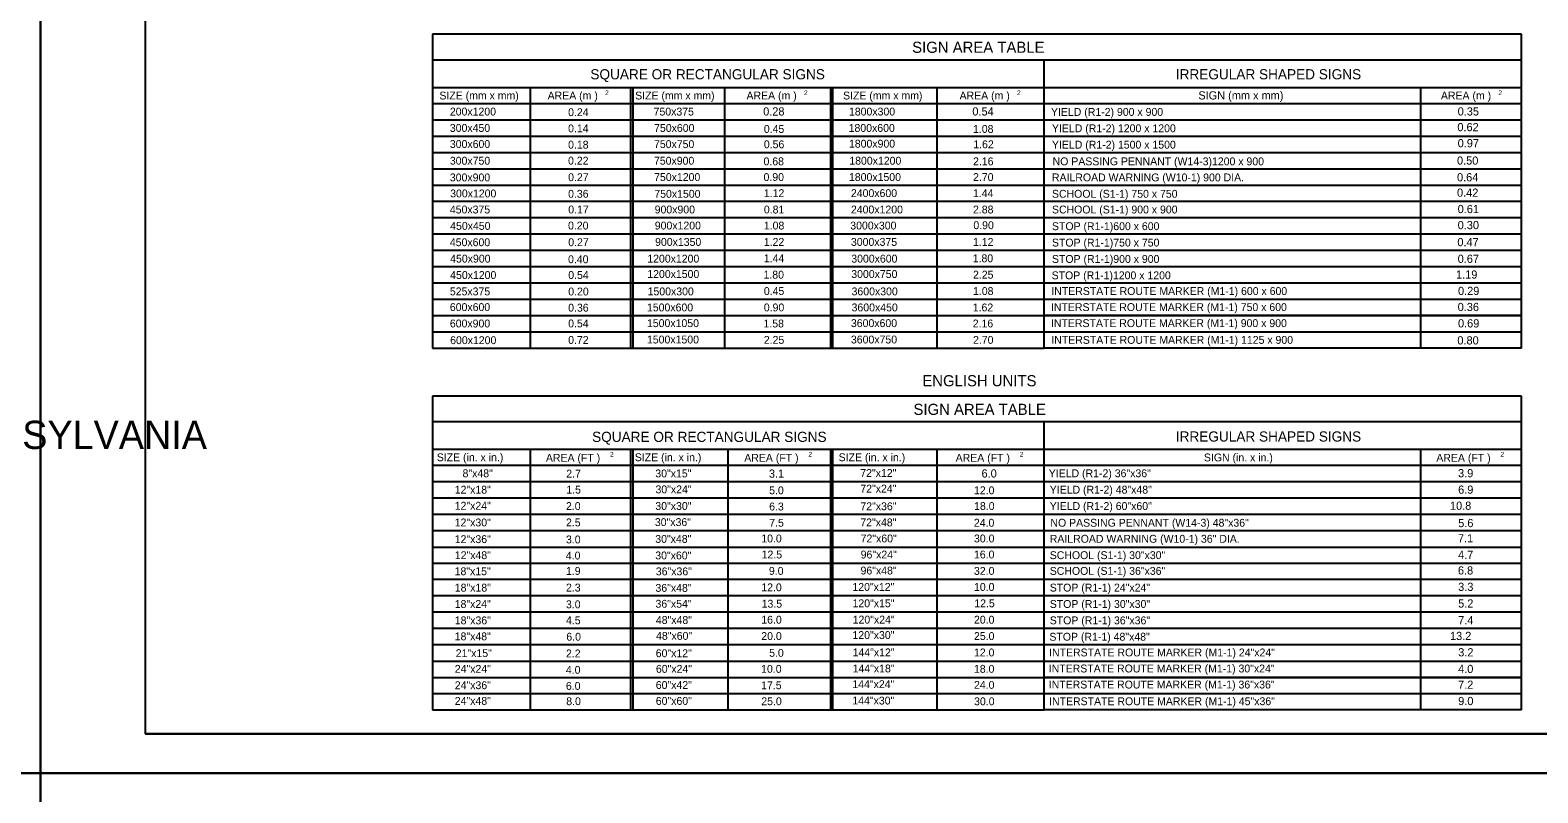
# Model space of a CAD drawing. Extents: x 644358 to 648627, y 294594 to 295782.
# Drawn here: x 646877 to 647453, y 295180 to 295471 of the extents above; entities that cross this region are included whole.
import ezdxf

# ---------------------------------------------------------------- set-up
doc = ezdxf.new("R2010")
doc.units = 0
for name, color, linetype in [('1', 7, 'Continuous'), ('2', 7, 'Continuous'), ('4', 7, 'Continuous'), ('PLT-BNDY', 7, 'Continuous')]:
    doc.layers.add(name, color=color, linetype=linetype)

msp = doc.modelspace()

# ---------------------------------------------------------------- linework, layer by layer
at = {"layer": '1'}
for p, q in [((646921.31, 295766.63), (646921.31, 295202.63)), ((647707.31, 295202.63), (646921.31, 295202.63)), ((646921.31, 295202.63), (647507.31, 295202.63))]:
    msp.add_line(p, q, dxfattribs=at)
at = {"layer": '2'}
for p, q in [((647030.99, 295469.63), (647030.99, 295349.88)), ((647446.74, 295469.63), (647030.99, 295469.63)), ((647446.74, 295349.88), (647446.74, 295469.63)), ((647446.74, 295459.75), (647030.99, 295459.75)), ((647264.37, 295459.75), (647264.37, 295349.88)), ((647030.99, 295449.38), (647446.74, 295449.38)), ((647068.24, 295449.38), (647068.24, 295349.88)), ((647106.62, 295449.38), (647106.62, 295349.88)), ((647107.49, 295449.38), (647107.49, 295349.88)), ((647142.49, 295449.38), (647142.49, 295349.88)), ((647182.99, 295449.38), (647182.99, 295349.88)), ((647183.74, 295449.38), (647183.74, 295349.88)), ((647223.49, 295449.38), (647223.49, 295349.88)), ((647408.37, 295349.88), (647408.37, 295449.38)), ((647030.99, 295443.25), (647446.74, 295443.25)), ((647030.99, 295437), (647446.74, 295437)), ((647030.99, 295430.75), (647446.74, 295430.75)), ((647030.99, 295424.5), (647446.74, 295424.5)), ((647030.99, 295418.25), (647446.74, 295418.25)), ((647030.99, 295412), (647446.74, 295412)), ((647030.99, 295405.88), (647446.74, 295405.88)), ((647030.99, 295399.75), (647446.74, 295399.75)), ((647030.99, 295393.5), (647446.74, 295393.5)), ((647030.99, 295387.25), (647446.74, 295387.25)), ((647030.99, 295381), (647446.74, 295381)), ((647030.99, 295374.75), (647446.74, 295374.75)), ((647030.99, 295368.5), (647446.74, 295368.5)), ((647264.37, 295368.5), (647446.74, 295368.5)), ((647030.99, 295362.25), (647446.74, 295362.25)), ((647446.74, 295362.25), (647264.37, 295362.25)), ((647030.99, 295356.13), (647446.74, 295356.13)), ((647030.99, 295349.88), (647264.37, 295349.88)), ((647446.74, 295349.88), (647264.37, 295349.88)), ((647030.99, 295331.57), (647030.99, 295211.82)), ((647446.74, 295331.57), (647030.99, 295331.57)), ((647446.74, 295211.82), (647446.74, 295331.57)), ((647446.74, 295321.69), (647030.99, 295321.69)), ((647264.37, 295321.69), (647264.37, 295211.82)), ((647030.99, 295311.32), (647446.74, 295311.32)), ((647068.24, 295311.32), (647068.24, 295211.82)), ((647106.62, 295311.32), (647106.62, 295211.82)), ((647107.49, 295311.32), (647107.49, 295211.82)), ((647143.79, 295311.32), (647143.79, 295211.82)), ((647182.99, 295311.32), (647182.99, 295211.82)), ((647183.74, 295311.32), (647183.74, 295211.82)), ((647223.49, 295311.32), (647223.49, 295211.82)), ((647408.37, 295211.82), (647408.37, 295311.32)), ((647030.99, 295305.19), (647446.74, 295305.19)), ((647030.99, 295298.94), (647446.74, 295298.94)), ((647030.99, 295292.69), (647446.74, 295292.69)), ((647030.99, 295286.44), (647446.74, 295286.44)), ((647030.99, 295280.19), (647446.74, 295280.19)), ((647030.99, 295273.94), (647446.74, 295273.94)), ((647030.99, 295267.82), (647446.74, 295267.82)), ((647030.99, 295261.69), (647446.74, 295261.69)), ((647030.99, 295255.44), (647446.74, 295255.44)), ((647030.99, 295249.19), (647446.74, 295249.19)), ((647030.99, 295242.94), (647446.74, 295242.94)), ((647030.99, 295236.69), (647446.74, 295236.69)), ((647030.99, 295230.44), (647446.74, 295230.44)), ((647264.37, 295230.44), (647446.74, 295230.44)), ((647030.99, 295224.19), (647446.74, 295224.19)), ((647446.74, 295224.19), (647264.37, 295224.19)), ((647030.99, 295218.07), (647446.74, 295218.07)), ((647030.99, 295211.82), (647264.37, 295211.82)), ((647446.74, 295211.82), (647264.37, 295211.82))]:
    msp.add_line(p, q, dxfattribs=at)
at = {"layer": '4'}
for p, q in [((647429.52, 295388.88), (647429.52, 295388.88)), ((647429.52, 295382.63), (647429.52, 295382.63)), ((647429.52, 295376.38), (647429.52, 295376.38)), ((647429.52, 295370.13), (647429.52, 295370.13)), ((647429.52, 295364), (647429.52, 295364)), ((647429.52, 295357.75), (647429.52, 295357.75)), ((647429.52, 295351.5), (647429.52, 295351.5)), ((647085.45, 295225.69), (647085.45, 295225.69)), ((647085.45, 295219.44), (647085.45, 295219.44)), ((647085.45, 295213.19), (647085.45, 295213.19))]:
    msp.add_line(p, q, dxfattribs=at)
at = {"layer": 'PLT-BNDY'}
for points in [[(646040.31, 295781.63), (646881.31, 295781.63), (646881.31, 295187.63), (646040.31, 295187.63)], [(646881.31, 295781.63), (647722.31, 295781.63), (647722.31, 295187.63), (646881.31, 295187.63)], [(646040.31, 295187.63), (646881.31, 295187.63), (646881.31, 294593.63), (646040.31, 294593.63)], [(646881.31, 295187.63), (647722.31, 295187.63), (647722.31, 294593.63), (646881.31, 294593.63)]]:
    msp.add_lwpolyline(points, close=True, dxfattribs=at)

# ---------------------------------------------------------------- texts
at = {"layer": '1'}
msp.add_text('COMMONWEALTH OF PENNSYLVANIA', height=10.7828, dxfattribs=at).set_placement((646678.9, 295311.36))
at = {"layer": '4'}
for s, height, p in [('SIGN AREA TABLE', 4.25, (647214.11, 295462.55)), ('SQUARE OR RECTANGULAR SIGNS', 3.8872, (647091.27, 295452.43)), ('IRREGULAR SHAPED SIGNS', 3.8872, (647314.77, 295452.43)), ('SIZE (mm x mm)', 3, (647033.62, 295444.75)), ('AREA (m )', 3, (647074.94, 295444.75)), ('2', 1.8, (647096.9, 295446.44)), ('SIZE (mm x mm)', 3, (647108.37, 295444.75)), ('AREA (m )', 3, (647150.87, 295444.75)), ('2', 1.8, (647172.82, 295446.44)), ('SIZE (mm x mm)', 3, (647187.74, 295444.75)), ('AREA (m )', 3, (647232.22, 295444.75)), ('2', 1.8, (647254.17, 295446.44)), ('SIGN (mm x mm)', 3.1252, (647323.37, 295444.75)), ('AREA (m )', 3, (647415.99, 295444.75)), ('2', 1.8, (647437.94, 295446.44)), ('200x1200', 3, (647037.62, 295438.63)), ('0.24', 3, (647082.76, 295438.38)), ('750x375', 3, (647115.41, 295438.63)), ('0.28', 3.125, (647157.24, 295438.63)), ('1800x300', 3, (647189.99, 295438.63)), ('0.54', 3.125, (647237.1, 295438.63)), ('YIELD (R1-2) 900 x 900 ', 3, (647267.12, 295438.5)), ('0.35', 3.125, (647422.39, 295438.63)), ('300x450', 3, (647037.62, 295432.38)), ('0.14', 3, (647082.76, 295432.22)), ('750x600', 3, (647115.6, 295432.38)), ('0.45', 3, (647157.49, 295432)), ('1800x600', 3, (647189.87, 295432.38)), ('1.08', 3, (647237.35, 295432)), ('YIELD (R1-2) 1200 x 1200 ', 3, (647267.49, 295432.25)), ('0.62', 3.125, (647422.27, 295432.63)), ('300x600', 3, (647037.62, 295426.25)), ('0.18', 3, (647082.76, 295426)), ('750x750', 3, (647115.55, 295426.2)), ('0.56', 3, (647157.5, 295426.13)), ('1800x900', 3, (647189.99, 295426.38)), ('1.62', 3, (647237.46, 295426.13)), ('YIELD (R1-2) 1500 x 1500 ', 3, (647267.49, 295426)), ('0.97', 3.125, (647422.39, 295426.5)), ('300x750', 3, (647037.62, 295419.88)), ('0.22', 3, (647082.74, 295419.9)), ('750x900', 3, (647115.55, 295419.88)), ('0.68', 3, (647157.37, 295419.63)), ('1800x1200', 3, (647190.12, 295419.88)), ('2.16', 3, (647237.36, 295419.63)), ('NO PASSING PENNANT (W14-3)1200 x 900 ', 3, (647267.74, 295419.63)), ('0.50', 3.125, (647422.14, 295419.88)), ('300x900', 3, (647037.62, 295413.5)), ('0.27', 3, (647082.78, 295413.58)), ('750x1200', 3, (647115.6, 295413.63)), ('0.90', 3, (647157.37, 295413.63)), ('1800x1500', 3, (647189.99, 295413.63)), ('2.70', 3, (647237.36, 295413.63)), ('RAILROAD WARNING (W10-1) 900 DIA.', 3, (647267.49, 295413.5)), ('0.64', 3.125, (647422.14, 295413.5)), ('300x1200', 3, (647037.74, 295407.38)), ('0.36', 3, (647082.76, 295407.25)), ('750x1500', 3, (647115.68, 295407.24)), ('1.12', 3, (647157.49, 295407.5)), ('2400x600', 3, (647190.74, 295407.5)), ('1.44', 3, (647237.35, 295407.5)), ('SCHOOL (S1-1) 750 x 750 ', 3, (647267.49, 295407.25)), ('0.42', 3.125, (647422.14, 295407.63)), ('450x375', 3, (647037.62, 295401.25)), ('0.17', 3, (647082.82, 295401.25)), ('900x900', 3, (647115.81, 295401.25)), ('0.81', 3, (647157.5, 295401.25)), ('2400x1200', 3, (647190.74, 295401.25)), ('2.88', 3, (647237.35, 295401.25)), ('SCHOOL (S1-1) 900 x 900 ', 3, (647267.49, 295401.25)), ('0.61', 3.125, (647422.39, 295401.38)), ('450x450', 3, (647037.74, 295395)), ('0.20', 3, (647082.74, 295395.13)), ('900x1200', 3, (647115.85, 295395.13)), ('1.08', 3, (647157.49, 295395.13)), ('3000x300', 3, (647190.49, 295395.13)), ('0.90', 3, (647237.49, 295395.26)), ('STOP (R1-1)600 x 600 ', 3, (647267.49, 295394.88)), ('0.30', 3.125, (647422.39, 295395.25)), ('450x600', 3, (647037.62, 295388.75)), ('0.27', 3, (647082.82, 295388.77)), ('900x1350', 3, (647115.98, 295388.88)), ('1.22', 3, (647157.49, 295388.88)), ('3000x375', 3, (647190.74, 295388.88)), ('1.12', 3, (647237.35, 295388.88)), ('STOP (R1-1)750 x 750', 3, (647267.49, 295388.63)), ('0.47', 3.125, (647422.27, 295388.75)), ('450x900', 3, (647037.74, 295382.5)), ('0.40', 3, (647082.74, 295382.25)), ('1200x1200', 3, (647112.99, 295382.5)), ('1.44', 3, (647157.49, 295382.63)), ('3000x600', 3, (647190.87, 295382.5)), ('1.80', 3, (647237.23, 295382.63)), ('STOP (R1-1)900 x 900 ', 3, (647267.49, 295382.38)), ('0.67', 3.125, (647422.39, 295382.38)), ('1200x1500', 3, (647112.99, 295376.63)), ('3000x750', 3, (647190.87, 295376.63)), ('1.19', 3.125, (647421.77, 295376.38)), ('450x1200', 3, (647037.74, 295376.25)), ('0.54', 3, (647082.82, 295376.25)), ('1.80', 3, (647157.37, 295376.38)), ('2.25', 3, (647237.35, 295376.38)), ('STOP (R1-1)1200 x 1200', 3, (647267.37, 295376.13)), ('525x375', 3, (647037.62, 295370)), ('0.20', 3, (647082.82, 295369.95)), ('1500x300', 3, (647113.12, 295370)), ('0.45', 3, (647157.49, 295370.13)), ('3600x300', 3, (647190.99, 295370)), ('1.08', 3, (647237.35, 295370.13)), ('INTERSTATE ROUTE MARKER (M1-1) 600 x 600 ', 3, (647267.24, 295370.13)), ('0.29', 3.125, (647422.52, 295370.13)), ('600x600', 3, (647037.62, 295364)), ('0.36', 3, (647082.79, 295363.79)), ('1500x600', 3, (647112.87, 295363.88)), ('0.90', 3, (647157.48, 295363.88)), ('3600x450', 3, (647190.99, 295363.88)), ('1.62', 3, (647237.25, 295363.88)), ('INTERSTATE ROUTE MARKER (M1-1) 750 x 600 ', 3, (647267.12, 295364)), ('0.36', 3.125, (647422.39, 295364)), ('600x900', 3, (647037.62, 295357.75)), ('0.54', 3, (647082.78, 295357.77)), ('1500x1050', 3, (647112.87, 295357.88)), ('1.58', 3, (647157.36, 295357.75)), ('3600x600', 3, (647190.74, 295357.88)), ('2.16', 3, (647237.25, 295357.75)), ('INTERSTATE ROUTE MARKER (M1-1) 900 x 900 ', 3, (647267.12, 295357.88)), ('0.69', 3.125, (647422.52, 295357.75)), ('600x1200', 3, (647037.74, 295351.38)), ('0.72', 3, (647082.78, 295351.47)), ('1500x1500', 3, (647112.87, 295351.63)), ('2.25', 3, (647157.49, 295351.5)), ('3600x750', 3, (647190.74, 295351.63)), ('2.70', 3, (647237.36, 295351.5)), ('INTERSTATE ROUTE MARKER (M1-1) 1125 x 900 ', 3, (647267.24, 295351.5)), ('0.80', 3.125, (647422.27, 295351.25)), ('ENGLISH UNITS', 4.25, (647218, 295335.29)), ('SIGN AREA TABLE', 4.25, (647214.62, 295324.36)), ('SQUARE OR RECTANGULAR SIGNS', 3.8872, (647091.92, 295314.05)), ('IRREGULAR SHAPED SIGNS', 3.8872, (647314.77, 295314.19)), ('SIZE (in. x in.)', 3, (647032.62, 295306.69)), ('AREA (FT )', 3, (647074.29, 295306.49)), ('2', 1.8, (647098.78, 295308.45)), ('SIZE (in. x in.)', 3, (647108.23, 295306.69)), ('AREA (FT )', 3, (647150.02, 295306.49)), ('2', 1.8, (647174.51, 295308.45)), ('SIZE (in. x in.)', 3, (647186.05, 295306.69)), ('AREA (FT )', 3, (647230.72, 295306.49)), ('2', 1.8, (647255.21, 295308.45)), ('SIGN (in. x in.)', 3, (647325.51, 295306.62)), ('AREA (FT )', 3, (647414.23, 295306.49)), ('2', 1.8, (647438.72, 295308.45)), ('8"x48"', 3, (647042.47, 295300.57)), ('2.7', 3, (647082.06, 295300.45)), ('30"x15"', 3, (647116.06, 295300.53)), ('3.1', 3.125, (647159.42, 295300.4)), ('72"x12"', 3, (647194.31, 295300.7)), ('6.0', 3.125, (647240.61, 295300.46)), ('YIELD (R1-2) 36"x36" ', 3, (647266.27, 295300.58)), ('3.9', 3.125, (647422.54, 295300.56)), ('12"x18"', 3, (647039.47, 295294.32)), ('1.5', 3, (647082.08, 295294.34)), ('30"x24"', 3, (647116.12, 295294.45)), ('5.0', 3, (647159.52, 295294.08)), ('72"x24"', 3, (647194.33, 295294.73)), ('12.0', 3, (647237.72, 295294.08)), ('YIELD (R1-2) 48"x48" ', 3, (647266.65, 295294.33)), ('6.9', 3.125, (647422.57, 295294.28)), ('12"x24"', 3, (647039.47, 295288.19)), ('2.0', 3, (647081.95, 295288.07)), ('30"x30"', 3, (647116.07, 295288.1)), ('6.3', 3, (647159.52, 295287.9)), ('72"x36"', 3, (647194.35, 295287.99)), ('18.0', 3, (647237.77, 295288.08)), ('YIELD (R1-2) 60"x60" ', 3, (647266.65, 295288.08)), ('10.8', 3.125, (647419.45, 295288.15)), ('12"x30"', 3, (647039.47, 295281.82)), ('2.5', 3, (647081.96, 295281.83)), ('30"x36"', 3, (647115.89, 295281.95)), ('7.5', 3, (647159.56, 295281.7)), ('72"x48"', 3, (647194.32, 295281.83)), ('24.0', 3, (647237.68, 295281.7)), ('NO PASSING PENNANT (W14-3) 48"x36" ', 3, (647266.9, 295281.7)), ('5.6', 3.125, (647422.59, 295281.53)), ('12"x36"', 3, (647039.47, 295275.44)), ('3.0', 3, (647081.95, 295275.32)), ('30"x48"', 3, (647116.04, 295275.53)), ('10.0', 3, (647156.52, 295275.7)), ('72"x60"', 3, (647194.44, 295275.71)), ('30.0', 3, (647237.72, 295275.7)), ('RAILROAD WARNING (W10-1) 36" DIA.', 3, (647266.65, 295275.58)), ('7.1', 3.125, (647422.49, 295275.72)), ('12"x48"', 3, (647039.51, 295269.32)), ('4.0', 3, (647081.9, 295269.19)), ('30"x60"', 3, (647116.04, 295269.23)), ('12.5', 3, (647156.65, 295269.58)), ('96"x24"', 3, (647194.46, 295269.58)), ('16.0', 3, (647237.72, 295269.58)), ('SCHOOL (S1-1) 30"x30" ', 3, (647266.65, 295269.33)), ('4.7', 3.125, (647422.54, 295269.42)), ('18"x15"', 3, (647039.44, 295263.19)), ('1.9', 3, (647081.94, 295263.32)), ('36"x36"', 3, (647116.24, 295263.15)), ('9.0', 3, (647159.43, 295263.33)), ('96"x48"', 3, (647194.41, 295263.47)), ('32.0', 3, (647237.72, 295263.33)), ('SCHOOL (S1-1) 36"x36" ', 3, (647266.65, 295263.33)), ('6.8', 3.125, (647422.48, 295263.45)), ('18"x18"', 3, (647039.5, 295256.94)), ('2.3', 3, (647081.96, 295256.96)), ('36"x48"', 3, (647116.12, 295256.85)), ('12.0', 3, (647156.52, 295257.05)), ('120"x12"', 3, (647191.3, 295257.21)), ('10.0', 3, (647237.72, 295257.2)), ('STOP (R1-1) 24"x24" ', 3, (647266.65, 295256.95)), ('3.3', 3.125, (647422.57, 295257.19)), ('18"x24"', 3, (647039.47, 295250.69)), ('3.0', 3, (647081.95, 295250.57)), ('36"x54"', 3, (647116.12, 295250.78)), ('13.5', 3, (647156.65, 295250.8)), ('120"x15"', 3, (647191.35, 295250.96)), ('12.5', 3, (647237.85, 295250.95)), ('STOP (R1-1) 30"x30"', 3, (647266.65, 295250.7)), ('5.2', 3.125, (647422.57, 295250.83)), ('18"x36"', 3, (647039.5, 295244.44)), ('4.5', 3, (647081.96, 295244.46)), ('48"x48"', 3, (647116.27, 295244.58)), ('16.0', 3, (647156.52, 295244.7)), ('120"x24"', 3, (647191.41, 295244.72)), ('20.0', 3, (647237.72, 295244.7)), ('STOP (R1-1) 36"x36" ', 3, (647266.65, 295244.45)), ('7.4', 3.125, (647422.57, 295244.45)), ('18"x48"', 3, (647039.46, 295238.34)), ('48"x60"', 3, (647116.34, 295238.53)), ('20.0', 3, (647156.52, 295238.45)), ('120"x30"', 3, (647191.33, 295238.84)), ('25.0', 3, (647237.72, 295238.45)), ('STOP (R1-1) 48"x48"', 3, (647266.52, 295238.2)), ('13.2', 3.125, (647419.46, 295238.45)), ('6.0', 3, (647082.09, 295238.21)), ('21"x15"', 3, (647039.86, 295231.94)), ('2.2', 3, (647081.95, 295231.83)), ('60"x12"', 3, (647116.22, 295231.9)), ('5.0', 3, (647159.52, 295232.05)), ('144"x12"', 3, (647191.38, 295232.22)), ('12.0', 3, (647237.72, 295232.2)), ('INTERSTATE ROUTE MARKER (M1-1) 24"x24" ', 3, (647266.4, 295232.2)), ('3.2', 3.125, (647422.6, 295232.2)), ('24"x24"', 3, (647039.51, 295225.94)), ('4.0', 3, (647081.92, 295225.57)), ('60"x24"', 3, (647116.29, 295225.95)), ('10.0', 3, (647156.46, 295225.95)), ('144"x18"', 3, (647191.38, 295226.09)), ('18.0', 3, (647237.71, 295225.95)), ('INTERSTATE ROUTE MARKER (M1-1) 30"x24" ', 3, (647266.27, 295226.08)), ('4.0', 3.125, (647422.55, 295225.87)), ('24"x36"', 3, (647039.51, 295219.69)), ('6.0', 3, (647081.93, 295219.44)), ('60"x42"', 3, (647116.24, 295219.78)), ('17.5', 3, (647156.47, 295219.68)), ('144"x24"', 3, (647191.28, 295220.09)), ('24.0', 3, (647237.73, 295219.83)), ('INTERSTATE ROUTE MARKER (M1-1) 36"x36" ', 3, (647266.27, 295219.95)), ('7.2', 3.125, (647422.54, 295219.83)), ('24"x48"', 3, (647039.5, 295213.71)), ('8.0', 3, (647082.06, 295213.59)), ('60"x60"', 3, (647116.24, 295213.7)), ('25.0', 3, (647156.52, 295213.58)), ('144"x30"', 3, (647191.28, 295213.84)), ('30.0', 3, (647237.77, 295213.55)), ('INTERSTATE ROUTE MARKER (M1-1) 45"x36" ', 3, (647266.4, 295213.58)), ('9.0', 3.125, (647422.59, 295213.61))]:
    msp.add_text(s, height=height, dxfattribs=at).set_placement(p)

doc.saveas('drawing.dxf')
